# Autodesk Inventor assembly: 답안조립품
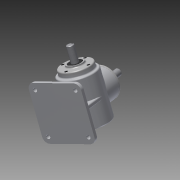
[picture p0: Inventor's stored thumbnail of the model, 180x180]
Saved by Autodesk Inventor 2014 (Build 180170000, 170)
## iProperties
Created: 2015-07
Part Number: 답안조립품
Document SubType Name: Assembly
Designer: Owner
Author: Owner
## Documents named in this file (14)
- C:\Documents and Settings\Owner\My Documents\Inventor\답안조립품.iam
- C:\Documents and Settings\Owner\My Documents\Inventor\450705V1008\본체.ipt
- C:\Documents and Settings\Owner\My Documents\Inventor\베어링 6203.ipt
- C:\Documents and Settings\Owner\My Documents\Inventor\커버.ipt
- C:\Documents and Settings\Owner\My Documents\Inventor\서브 축.ipt
- 서브 축.ipt
- C:\Documents and Settings\Owner\My Documents\Inventor\메인 축.ipt
- 메인 축.ipt
- C:\Documents and Settings\Owner\My Documents\Inventor\서브 베벨기어.ipt
- C:\Documents and Settings\Owner\My Documents\Inventor\메인 베벨기어.ipt
- C:\Documents and Settings\Owner\My Documents\Inventor\오일실.ipt
- C:\Documents and Settings\Owner\My Documents\Inventor\키 5x5.ipt
- C:\Documents and Settings\Owner\My Documents\Inventor\키 4x4.ipt
- C:\Documents and Settings\Owner\My Documents\Inventor\M4.ipt
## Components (8 placed, 1 different names)
1. M4:1
2. M4:3
3. M4:4
4. M4:5
5. M4:2
6. M4:6
7. M4:7
8. M4:8
